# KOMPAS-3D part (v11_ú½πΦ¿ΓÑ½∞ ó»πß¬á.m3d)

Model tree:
1. Эскиз:1
2. Операция выдавливания:1
     Расстояние 1 = 19
3. Скругление:2
     Радиус = 2
4. Эскиз:5
5. Операция выдавливания:2
     Расстояние 1 = 40; Расстояние 2 = 68
6. Эскиз:6
7. Операция вращения:2
     Угол 1 = 115; Угол 2 = 360
8. Эскиз:8
9. Операция выдавливания:4
     Расстояние 1 = 4; Расстояние 2 = 15
10. Эскиз:9
11. Операция выдавливания:5
     Расстояние 1 = 40; Расстояние 2 = 15
12. Эскиз:10
13. Вырезать элемент выдавливания:2
     Расстояние 1 = 13
14. Эскиз:11
15. Вырезать элемент выдавливания:3
     Расстояние 2 = 3.6; Расстояние 1 = 13
16. Эскиз:12
17. Вырезать элемент выдавливания:4
     Расстояние 2 = 29.8908; Расстояние 1 = 57.263
18. Фаска:1
     Угол = 45; Длина 1 = 0.5; Длина 2 = 0.5
19. Фаска:2
     Угол = 60; Длина 1 = 2.8; Длина 2 = 4.84974
20. Скругление:1
     Радиус = 2
21. Фаска:3
     Угол = 45; Длина 1 = 0.6; Длина 2 = 0.6
22. Фаска:4
     Угол = 45; Длина 1 = 1.5; Длина 2 = 1.5
23. Эскиз:14
24. Операция выдавливания:7
     Расстояние 1 = 19; Расстояние 2 = 13
25. Эскиз:16
26. Эскиз:17
27. Вырезать элемент выдавливания:6
     Расстояние 2 = 29.8908; Расстояние 1 = 30
28. Вырезать элемент выдавливания:7
     Расстояние 2 = 29.8908; Расстояние 1 = 19
29. Эскиз:18
30. Вырезать элемент выдавливания:8
     Расстояние 2 = 29.9215; Расстояние 1 = 19
31. Эскиз:19
32. Вырезать элемент выдавливания:9
     Расстояние 2 = 25.1801; Расстояние 1 = 19
33. Фаска:5
     Угол = 45; Длина 1 = 1.5; Длина 2 = 1.5
34. Фаска:6
     Угол = 45; Длина 1 = 1; Длина 2 = 1
35. Фаска:7
     Угол = 45; Длина 1 = 1; Длина 2 = 1
36. Фаска:8
     Угол = 45; Длина 1 = 1.5; Длина 2 = 1.5
37. Скругление:3
     Радиус = 5
38. Скругление:4
     Радиус = 3
39. Эскиз:20
40. Эскиз:22
41. Операция выдавливания:8
     Расстояние 1 = 8; Расстояние 2 = 8
42. Скругление:5
     Радиус = 2
43. Скругление:7
     Радиус = 3
44. Скругление:8
     Радиус = 1
45. Скругление:9
     Радиус = 1

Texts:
  Линия-выноска #1
  Линия-выноска #2
  Линия-выноска #3
  Отклонения формы и база
  Марка координационной оси
  Марка/позиционное обозначение с линией-выноской
  Марка/позиционное обозначение на линии
  Марка/позиционное обозначение без линии-выноски
  Текст на чертеже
